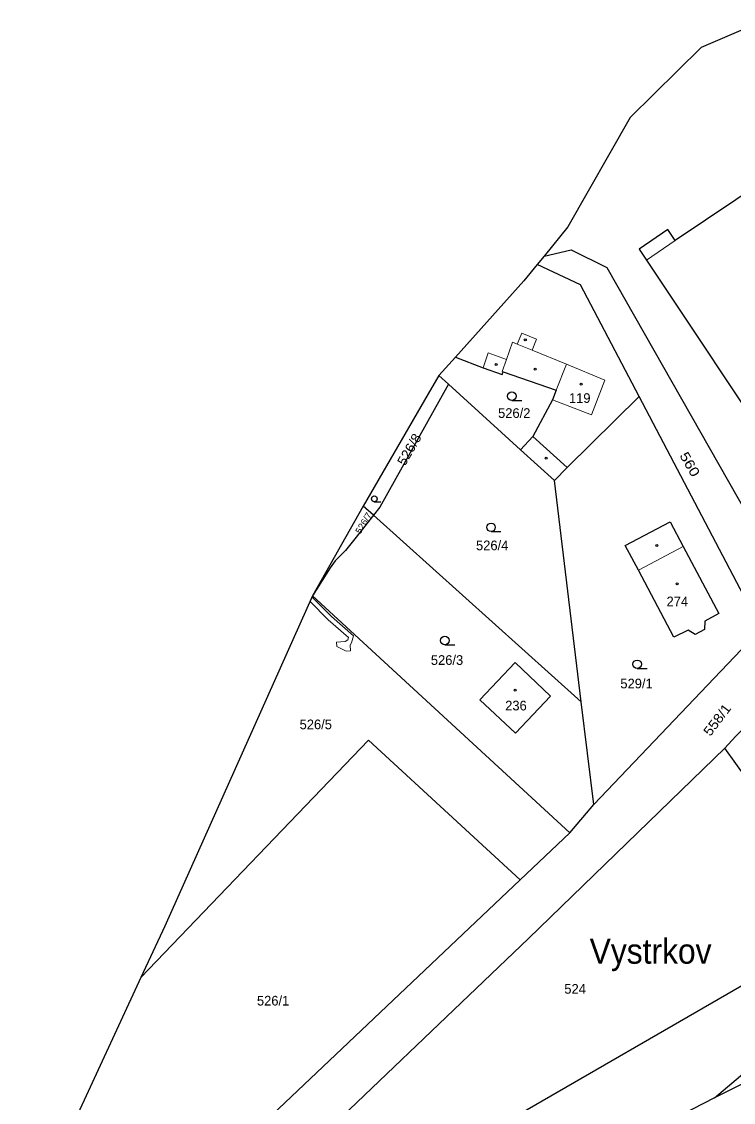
# Model space of a CAD drawing. Extents: x -754445 to -751443, y -1030748 to -1028224.
# Drawn here: x -752676 to -752550.8, y -1028524.8 to -1028334.7 of the extents above; entities that cross this region are included whole.
import ezdxf
from ezdxf.enums import TextEntityAlignment as Align

# ---------------------------------------------------------------- set-up
doc = ezdxf.new("R2010")
doc.units = 0
doc.header["$LTSCALE"] = 0.68
for name, color, linetype, lineweight in [('1', 7, 'Continuous', 25), ('13', 7, 'Continuous', 13), ('3', 7, 'Continuous', 25), ('4', 7, 'Continuous', 13), ('5', 7, 'Continuous', 25), ('7', 7, 'Continuous', 13)]:
    doc.layers.add(name, color=color, linetype=linetype, lineweight=lineweight)
doc.layers.add('2', color=7, linetype='Continuous')

msp = doc.modelspace()

# ---------------------------------------------------------------- linework, layer by layer
at = {"layer": '1'}
for p, q in [((-752579.96, -1028370.78), (-752584.13, -1028375.9)), ((-752584.13, -1028375.9), (-752585.35, -1028377.4)), ((-752587.69, -1028380.27), (-752599.72, -1028393.67)), ((-752602.64, -1028396.93), (-752604.47, -1028400.11)), ((-752604.47, -1028400.11), (-752615.9, -1028419.9)), ((-752588.24, -1028409.99), (-752582.31, -1028415.38)), ((-752577.58, -1028454.31), (-752582.31, -1028415.38)), ((-752534.98, -1028486.77), (-752552.32, -1028462.48)), ((-752588.3, -1028485.62), (-752579.59, -1028477.36)), ((-752639.29, -1028533.95), (-752588.3, -1028485.62)), ((-752655.01, -1028502.82), (-752675.98, -1028548.14)), ((-752616.34, -1028542.9), (-752546.71, -1028502.68)), ((-752554.14, -1028523.99), (-752529.24, -1028502.86))]:
    msp.add_line(p, q, dxfattribs=at)
for points in [[(-752545.81, -1028334.65), (-752556.51, -1028339.21), (-752568.95, -1028351.49), (-752579.96, -1028370.78)], [(-752514.69, -1028338.65), (-752515.41, -1028337.64), (-752531.29, -1028348.38), (-752529.08, -1028351.68), (-752561.06, -1028373.16), (-752562.37, -1028371.21), (-752567.41, -1028374.68), (-752566.1, -1028376.62), (-752542.38, -1028412.28), (-752543.51, -1028413.04), (-752542.01, -1028415.25), (-752503.1, -1028388.94), (-752494.07, -1028382.8)], [(-752584.13, -1028375.9), (-752579.37, -1028374.82), (-752573.06, -1028377.89), (-752540.27, -1028435.69)], [(-752567.4, -1028400.59), (-752577.71, -1028380.96), (-752585.35, -1028377.4), (-752587.69, -1028380.27)], [(-752599.72, -1028393.67), (-752602.64, -1028396.93), (-752600.95, -1028398.46), (-752588.24, -1028409.99)], [(-752599.72, -1028393.67), (-752594.84, -1028395.55), (-752591.49, -1028396.72), (-752591.32, -1028396.25), (-752581.97, -1028399.51), (-752582.62, -1028401.18), (-752586.09, -1028407.62), (-752588.24, -1028409.99)], [(-752600.95, -1028398.46), (-752613.02, -1028420.1), (-752614.12, -1028421.5)], [(-752582.31, -1028415.38), (-752580.04, -1028413.12), (-752567.4, -1028400.59)], [(-752575.39, -1028472.41), (-752545.95, -1028441.45), (-752567.4, -1028400.59)], [(-752614.12, -1028421.5), (-752615.9, -1028419.9), (-752624.83, -1028435.7)], [(-752624.83, -1028435.7), (-752579.59, -1028477.36), (-752575.39, -1028472.41), (-752577.58, -1028454.31), (-752614.12, -1028421.5), (-752617.38, -1028425.65)], [(-752617.38, -1028425.65), (-752619.02, -1028427.68), (-752620.48, -1028429.16), (-752620.83, -1028429.53), (-752621.75, -1028430.73), (-752624.83, -1028435.7)], [(-752624.83, -1028435.7), (-752650.82, -1028493.76), (-752655.01, -1028502.82)], [(-752504.02, -1028487.38), (-752492.89, -1028483.87), (-752491.92, -1028483.53), (-752532.24, -1028441.9), (-752550.47, -1028460.4), (-752552.32, -1028462.48)], [(-752588.3, -1028485.62), (-752614.97, -1028461.06), (-752655.01, -1028502.82)], [(-752552.32, -1028462.48), (-752586.88, -1028495.96), (-752630.14, -1028537.36)], [(-752534.88, -1028531.48), (-752531.14, -1028512.51), (-752554.14, -1028523.99), (-752562, -1028528.01)]]:
    msp.add_lwpolyline(points, dxfattribs=at)
for points in [[(-752557.54, -1028442.48), (-752558.81, -1028441.71), (-752561.29, -1028442.96), (-752567.54, -1028431.17), (-752569.85, -1028426.81), (-752561.95, -1028422.65), (-752559.64, -1028427.01), (-752553.39, -1028438.8), (-752555.86, -1028440.12), (-752555.9, -1028441.58)], [(-752589.16, -1028459.86), (-752582.96, -1028453.3), (-752589.21, -1028447.39), (-752595.41, -1028453.95)]]:
    msp.add_lwpolyline(points, close=True, dxfattribs=at)
at = {"layer": '13'}
msp.add_lwpolyline([(-752621.51, -1028439.29), (-752624.92, -1028435.89), (-752625.27, -1028436.67), (-752622.06, -1028439.88), (-752618.52, -1028442.98), (-752618.64, -1028443.44), (-752619.08, -1028443.68), (-752620.64, -1028443.82), (-752620.57, -1028444.61), (-752618.92, -1028445.41), (-752618.13, -1028445.33), (-752618.23, -1028444.38), (-752617.95, -1028443.97), (-752617.62, -1028442.71)], close=True, dxfattribs=at)
at = {"layer": '3'}
for p, q in [((-752589.783, -1028401.29), (-752588.033, -1028401.29)), ((-752613.965, -1028419.11), (-752612.793, -1028419.11)), ((-752593.443, -1028424.37), (-752591.693, -1028424.37)), ((-752601.553, -1028444.29), (-752599.803, -1028444.29)), ((-752567.753, -1028448.47), (-752566.003, -1028448.47))]:
    msp.add_line(p, q, dxfattribs=at)
for centre, radius in [((-752589.7829, -1028400.5398), 0.75), ((-752613.9652, -1028418.6074), 0.5025), ((-752593.4429, -1028423.6198), 0.75), ((-752601.5529, -1028443.5398), 0.75), ((-752567.7529, -1028447.7198), 0.75)]:
    msp.add_circle(centre, radius, dxfattribs=at)
at = {"layer": '4'}
for p, q in [((-752561.06, -1028373.16), (-752566.1, -1028376.62)), ((-752588.04, -1028389.45), (-752588.83, -1028391.4)), ((-752588.04, -1028389.45), (-752585.45, -1028390.51)), ((-752589.67, -1028391.05), (-752590.72, -1028394.07)), ((-752589.67, -1028391.05), (-752588.83, -1028391.4)), ((-752588.83, -1028391.4), (-752586.24, -1028392.46)), ((-752585.45, -1028390.51), (-752586.24, -1028392.46)), ((-752593.93, -1028392.95), (-752594.84, -1028395.55)), ((-752590.72, -1028394.07), (-752593.93, -1028392.95)), ((-752586.24, -1028392.46), (-752580.2, -1028394.94)), ((-752590.72, -1028394.07), (-752591.46, -1028396.2)), ((-752580.2, -1028394.94), (-752581.97, -1028399.51)), ((-752580.2, -1028394.94), (-752573.45, -1028397.72)), ((-752591.32, -1028396.25), (-752591.46, -1028396.2)), ((-752575.8, -1028403.81), (-752573.45, -1028397.72)), ((-752582.62, -1028401.18), (-752575.8, -1028403.81)), ((-752580.04, -1028413.12), (-752586.09, -1028407.62)), ((-752567.54, -1028431.17), (-752559.64, -1028427.01))]:
    msp.add_line(p, q, dxfattribs=at)
at = {"layer": '5'}
for centre in [(-752587.4168, -1028390.6192), (-752592.5268, -1028394.9592), (-752585.6668, -1028395.7892), (-752577.5768, -1028398.4292), (-752583.7668, -1028411.4492), (-752564.2968, -1028426.7992), (-752560.6968, -1028433.5392), (-752589.1968, -1028452.2592)]:
    msp.add_circle(centre, 0.175, dxfattribs=at)

# ---------------------------------------------------------------- texts
at = {"layer": '2'}
for s, p in [('119', (-752577.849, -1028401.73)), ('526/2', (-752589.36, -1028404.37)), ('526/4', (-752593.24, -1028427.65)), ('274', (-752560.689, -1028437.51)), ('526/3', (-752601.18, -1028447.82)), ('529/1', (-752567.86, -1028451.95)), ('236', (-752589.059, -1028455.83)), ('526/5', (-752624.26, -1028459.14)), ('524', (-752578.659, -1028505.67)), ('526/1', (-752631.76, -1028507.75))]:
    msp.add_text(s, height=1.7, dxfattribs=at).set_placement(p, align=Align.CENTER)
for s, height, rotation, width, p in [('526/8', 1.7, 60, 1.05, (-752607.0798, -1028410.341)), ('560', 1.7, 300, 1.2, (-752559.2221, -1028412.9575)), ('526/7', 1.14, 59, 1.05, (-752615.3735, -1028423.1671)), ('558/1', 1.7, 53, 1.1, (-752553.0039, -1028458))]:
    msp.add_text(s, height=height, rotation=rotation, dxfattribs=dict(at, width=width)).set_placement(p, align=Align.CENTER)
at = {"layer": '7', "width": 0.95}
msp.add_text('Vystrkov', height=4.4, dxfattribs=at).set_placement((-752565.39, -1028500.388), align=Align.CENTER)

doc.saveas('drawing.dxf')
